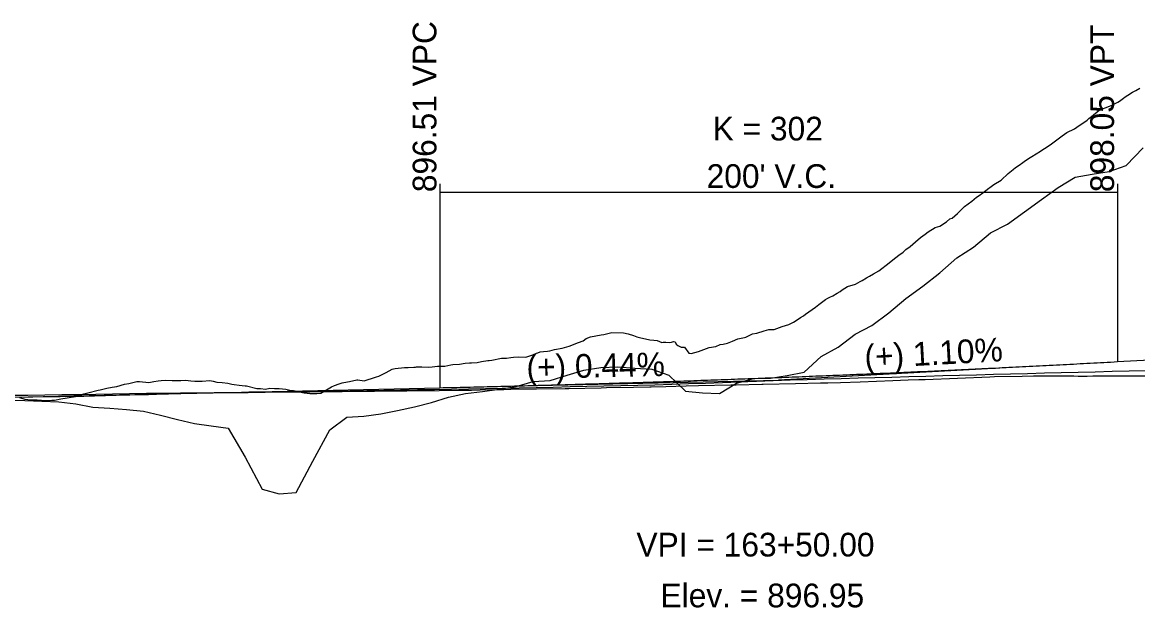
# Model space of a CAD drawing. Extents: x 1475774 to 1484571, y 1098511 to 1113011.
# Drawn here: x 1478897.8 to 1479227, y 1103928.9 to 1104101.6 of the extents above; entities that cross this region are included whole.
import ezdxf

# ---------------------------------------------------------------- set-up
doc = ezdxf.new("R2010")
doc.units = 0
for name, color, linetype in [('RD_DDB_GradeTX', 7, 'Continuous'), ('RD_DDB_PointTX', 7, 'Continuous'), ('RD_DDB_Profile_EX', 7, 'Continuous'), ('RD_DDB_Profile_Lbl', 7, 'Continuous'), ('RD_DDB_Profile_PR', 7, 'Continuous'), ('RD_DDB_StripGrade', 7, 'Continuous'), ('RD_DDB_VCLbl', 7, 'Continuous'), ('RD_Sketch2', 7, 'Continuous'), ('RD_Sketch3', 7, 'Continuous')]:
    doc.layers.add(name, color=color, linetype=linetype)

msp = doc.modelspace()

# ---------------------------------------------------------------- linework, layer by layer
at = {"layer": 'RD_DDB_GradeTX'}
for p in [(1479200.86, 1104000.39), (1479041, 1103994.24)]:
    msp.add_line(p, (1479120.98, 1103996), dxfattribs=at)
at = {"layer": 'RD_DDB_PointTX'}
for points in [[(1478894.42, 1103991.56), (1478899.42, 1103991.63), (1478904.42, 1103991.71), (1478909.42, 1103991.78), (1478914.42, 1103991.85), (1478919.42, 1103991.92), (1478924.42, 1103992), (1478929.42, 1103992.07), (1478934.42, 1103992.15), (1478939.42, 1103992.2), (1478944.42, 1103992.25), (1478949.42, 1103992.3), (1478954.42, 1103992.35), (1478959.42, 1103992.39), (1478964.42, 1103992.44), (1478969.42, 1103992.49), (1478974.42, 1103992.54), (1478979.42, 1103992.6), (1478984.42, 1103992.69), (1478989.42, 1103992.78), (1478994.42, 1103992.87), (1478999.42, 1103992.96), (1479004.42, 1103993.05), (1479009.42, 1103993.14), (1479014.42, 1103993.23), (1479019.42, 1103993.32), (1479024.42, 1103993.41), (1479029.42, 1103993.5), (1479034.42, 1103993.59), (1479039.42, 1103993.7), (1479044.42, 1103993.8), (1479049.42, 1103993.91), (1479054.42, 1103994.01), (1479059.42, 1103994.12), (1479064.42, 1103994.23), (1479069.42, 1103994.34), (1479074.42, 1103994.44), (1479079.42, 1103994.55), (1479084.42, 1103994.65), (1479089.42, 1103994.83), (1479094.42, 1103995.01), (1479099.42, 1103995.19), (1479104.42, 1103995.37), (1479109.42, 1103995.54), (1479114.42, 1103995.72), (1479119.42, 1103995.9), (1479124.42, 1103996.08), (1479129.42, 1103996.26), (1479134.42, 1103996.43), (1479139.42, 1103996.56), (1479144.42, 1103996.7), (1479149.42, 1103996.83), (1479154.42, 1103996.96), (1479159.42, 1103997.11), (1479164.42, 1103997.24)], [(1479164.42, 1103997.24), (1479169.42, 1103997.38), (1479174.42, 1103997.51), (1479179.42, 1103997.65), (1479184.42, 1103997.79), (1479189.42, 1103997.92), (1479194.42, 1103998.04), (1479199.42, 1103998.17), (1479204.42, 1103998.29), (1479209.42, 1103998.41), (1479214.42, 1103998.53), (1479219.42, 1103998.66), (1479224.42, 1103998.78), (1479229.42, 1103998.91)]]:
    msp.add_lwpolyline(points, dxfattribs=at)
at = {"layer": 'RD_DDB_Profile_EX'}
for points in [[(1479163.54, 1104023.72), (1479168.54, 1104027.68), (1479173.54, 1104032.08), (1479178.54, 1104035.32), (1479183.54, 1104039.47), (1479188.54, 1104042.1), (1479193.54, 1104045.74), (1479198.54, 1104049.38), (1479203.54, 1104052.85), (1479208.54, 1104055.91), (1479213.54, 1104056.84), (1479218.54, 1104057.57), (1479223.54, 1104059.33), (1479228.54, 1104064.6)], [(1478893.54, 1103990.17), (1478898.54, 1103990.02), (1478903.54, 1103989.87), (1478908.54, 1103989.67), (1478913.54, 1103989.07), (1478918.54, 1103988.09), (1478923.54, 1103987.72), (1478928.54, 1103987.36), (1478933.54, 1103986.85), (1478938.54, 1103985.66), (1478943.54, 1103984.47), (1478948.54, 1103983.27), (1478953.54, 1103982.51), (1478958.54, 1103981.89), (1478963.54, 1103973.34), (1478968.54, 1103963.9), (1478973.54, 1103962.48), (1478978.54, 1103962.86), (1478983.54, 1103972.13), (1478988.54, 1103981.41), (1478993.54, 1103985.12), (1478998.54, 1103985.37), (1479003.54, 1103986.11), (1479008.54, 1103987.1), (1479013.54, 1103988.17), (1479018.54, 1103989.41), (1479023.54, 1103991), (1479028.54, 1103992.06), (1479033.54, 1103992.7), (1479038.54, 1103993.34), (1479043.54, 1103994.15), (1479048.54, 1103995.63), (1479053.54, 1103995.94), (1479058.54, 1103997.5), (1479063.54, 1103999.02), (1479068.54, 1103999.81), (1479073.54, 1103999.94), (1479078.54, 1103999.54), (1479083.54, 1103999.32), (1479088.54, 1103997.52), (1479093.54, 1103992.76), (1479098.54, 1103992.34), (1479103.54, 1103992.13), (1479108.54, 1103995.11), (1479113.54, 1103996.49), (1479118.54, 1103996.66), (1479123.54, 1103997.43), (1479128.54, 1103998.35), (1479133.54, 1104002.98), (1479138.54, 1104005.74), (1479143.54, 1104009.61), (1479148.54, 1104012.14), (1479153.54, 1104015.92), (1479158.54, 1104020.12), (1479163.54, 1104023.72)]]:
    msp.add_lwpolyline(points, dxfattribs=at)
at = {"layer": 'RD_DDB_Profile_PR'}
for p, q in [((1479220.98, 1104001.5), (1479495.98, 1104016.62)), ((1479220.98, 1104001.5), (1479495.98, 1104016.62)), ((1478430.98, 1103980.88), (1479020.98, 1103993.81)), ((1478430.98, 1103980.88), (1479020.98, 1103993.81))]:
    msp.add_line(p, q, dxfattribs=at)
msp.add_spline([(1479020.98, 1103993.81), (1479024.98, 1103993.89), (1479028.98, 1103993.99), (1479032.98, 1103994.08), (1479036.98, 1103994.18), (1479040.98, 1103994.28), (1479044.98, 1103994.38), (1479048.98, 1103994.48), (1479052.98, 1103994.59), (1479056.98, 1103994.7), (1479060.98, 1103994.81), (1479064.98, 1103994.93), (1479068.98, 1103995.05), (1479072.98, 1103995.17), (1479076.98, 1103995.29), (1479080.98, 1103995.42), (1479084.98, 1103995.55), (1479088.98, 1103995.68), (1479092.98, 1103995.81), (1479096.98, 1103995.95), (1479100.98, 1103996.09), (1479104.98, 1103996.23), (1479108.98, 1103996.38), (1479112.98, 1103996.52), (1479116.98, 1103996.67), (1479120.98, 1103996.82), (1479124.98, 1103996.98), (1479128.98, 1103997.14), (1479132.98, 1103997.3), (1479136.98, 1103997.46), (1479140.98, 1103997.63), (1479144.98, 1103997.8), (1479148.98, 1103997.97), (1479152.98, 1103998.14), (1479156.98, 1103998.32), (1479160.98, 1103998.5), (1479164.98, 1103998.68), (1479168.98, 1103998.86), (1479172.98, 1103999.05), (1479176.98, 1103999.24), (1479180.98, 1103999.43), (1479184.98, 1103999.62), (1479188.98, 1103999.82), (1479192.98, 1104000.02), (1479196.98, 1104000.23), (1479200.98, 1104000.43), (1479204.98, 1104000.64), (1479208.98, 1104000.85), (1479212.98, 1104001.06), (1479216.98, 1104001.28), (1479220.98, 1104001.5)], degree=3, dxfattribs=at)
msp.add_spline([(1479020.98, 1103993.81), (1479024.98, 1103993.89), (1479028.98, 1103993.99), (1479032.98, 1103994.08), (1479036.98, 1103994.18), (1479040.98, 1103994.28), (1479044.98, 1103994.38), (1479048.98, 1103994.48), (1479052.98, 1103994.59), (1479056.98, 1103994.7), (1479060.98, 1103994.81), (1479064.98, 1103994.93), (1479068.98, 1103995.05), (1479072.98, 1103995.17), (1479076.98, 1103995.29), (1479080.98, 1103995.42), (1479084.98, 1103995.55), (1479088.98, 1103995.68), (1479092.98, 1103995.81), (1479096.98, 1103995.95), (1479100.98, 1103996.09), (1479104.98, 1103996.23), (1479108.98, 1103996.38), (1479112.98, 1103996.52), (1479116.98, 1103996.67), (1479120.98, 1103996.82), (1479124.98, 1103996.98), (1479128.98, 1103997.14), (1479132.98, 1103997.3), (1479136.98, 1103997.46), (1479140.98, 1103997.63), (1479144.98, 1103997.8), (1479148.98, 1103997.97), (1479152.98, 1103998.14), (1479156.98, 1103998.32), (1479160.98, 1103998.5), (1479164.98, 1103998.68), (1479168.98, 1103998.86), (1479172.98, 1103999.05), (1479176.98, 1103999.24), (1479180.98, 1103999.43), (1479184.98, 1103999.62), (1479188.98, 1103999.82), (1479192.98, 1104000.02), (1479196.98, 1104000.23), (1479200.98, 1104000.43), (1479204.98, 1104000.64), (1479208.98, 1104000.85), (1479212.98, 1104001.06), (1479216.98, 1104001.28), (1479220.98, 1104001.5)], degree=3, dxfattribs=at)
at = {"layer": 'RD_DDB_VCLbl'}
for p, q in [((1479020.98, 1104054), (1479020.98, 1103993.81)), ((1479220.98, 1104054), (1479220.98, 1104001.5)), ((1479020.98, 1104051.5), (1479220.98, 1104051.5))]:
    msp.add_line(p, q, dxfattribs=at)
at = {"layer": 'RD_Sketch2'}
msp.add_lwpolyline([(1478896.9, 1103990.98), (1478900.87, 1103991.08), (1478906.43, 1103991.17), (1478908.88, 1103991.21), (1478915.07, 1103991.31), (1478915.95, 1103991.33), (1478925.47, 1103991.59), (1478933.62, 1103991.8), (1478935, 1103991.83), (1478937.38, 1103991.87), (1478944.52, 1103992.05), (1478954.05, 1103992.28), (1478958.71, 1103992.4), (1478959.2, 1103992.41), (1478963.57, 1103992.52), (1478964.65, 1103992.55), (1478973.1, 1103992.55), (1478976.78, 1103992.56), (1478978.55, 1103992.58), (1478982.62, 1103992.62), (1478992.14, 1103992.71), (1479001.67, 1103992.79), (1479006.63, 1103992.87), (1479011.23, 1103992.91), (1479020.79, 1103993.01), (1479026.62, 1103993.07), (1479028.65, 1103993.1), (1479030.35, 1103993.12), (1479032.91, 1103993.14), (1479039.92, 1103993.29), (1479041.93, 1103993.33), (1479049.48, 1103993.44), (1479057.95, 1103993.57), (1479059.04, 1103993.59), (1479068.6, 1103993.8), (1479070.22, 1103993.84), (1479078.16, 1103993.96), (1479082.99, 1103994.04), (1479083.41, 1103994.04), (1479087.72, 1103994.18), (1479093.67, 1103994.36), (1479097.29, 1103994.43), (1479106.85, 1103994.62), (1479108.5, 1103994.66), (1479116, 1103994.88), (1479116.41, 1103994.89), (1479125.97, 1103995.07), (1479133.35, 1103995.22), (1479133.94, 1103995.23), (1479135.53, 1103995.26), (1479139.27, 1103995.33), (1479145.09, 1103995.56), (1479154.66, 1103995.93), (1479159.2, 1103996.11), (1479162.32, 1103996.18), (1479164.22, 1103996.26), (1479173.78, 1103996.65), (1479183.34, 1103997.04), (1479184.68, 1103997.09), (1479192.9, 1103997.21), (1479196.24, 1103997.27), (1479202.46, 1103997.3), (1479208.07, 1103997.34), (1479209.43, 1103997.22), (1479210.09, 1103997.23), (1479212.03, 1103997.17), (1479213.68, 1103997.31), (1479221.59, 1103997.34), (1479231.15, 1103997.35)], dxfattribs=at)
at = {"layer": 'RD_Sketch3'}
msp.add_lwpolyline([(1478896.9, 1103990.87), (1478898.5, 1103990.47), (1478899.34, 1103990.33), (1478899.91, 1103990.24), (1478902.1, 1103990.27), (1478904.77, 1103990.02), (1478906.43, 1103990.11), (1478907.27, 1103990.16), (1478909.08, 1103990.5), (1478913.5, 1103991.21), (1478913.99, 1103991.37), (1478914.74, 1103991.63), (1478915.95, 1103991.97), (1478917.11, 1103992.29), (1478920.18, 1103993.07), (1478920.71, 1103993.17), (1478922.67, 1103993.7), (1478924.31, 1103993.94), (1478925.63, 1103994.18), (1478927.91, 1103994.82), (1478929.17, 1103995.05), (1478931.52, 1103995.63), (1478932.35, 1103995.61), (1478935.12, 1103995.36), (1478936.54, 1103995.65), (1478937.85, 1103995.81), (1478938.72, 1103995.91), (1478940.02, 1103995.99), (1478942, 1103995.94), (1478942.31, 1103995.94), (1478942.92, 1103995.95), (1478944.52, 1103995.98), (1478945.91, 1103996.02), (1478947.47, 1103995.88), (1478948.7, 1103995.73), (1478949.51, 1103995.76), (1478950.87, 1103995.71), (1478953.11, 1103995.97), (1478954.05, 1103995.75), (1478955.21, 1103995.47), (1478956.7, 1103995.35), (1478958.41, 1103995.1), (1478959.55, 1103994.82), (1478960.3, 1103994.74), (1478961.72, 1103994.56), (1478963.57, 1103994.38), (1478963.9, 1103994.34), (1478967, 1103993.6), (1478968.05, 1103993.58), (1478969.49, 1103993.35), (1478970.84, 1103993.66), (1478972.23, 1103993.6), (1478973.1, 1103993.61), (1478973.52, 1103993.62), (1478975.53, 1103993.34), (1478976.76, 1103993.1), (1478977.77, 1103993), (1478980.9, 1103992.33), (1478981.86, 1103992.17), (1478982.62, 1103992.14), (1478984.72, 1103992.07), (1478985.83, 1103992.23), (1478989.04, 1103994.11), (1478989.94, 1103994.43), (1478991.32, 1103994.95), (1478992.14, 1103995.25), (1478992.62, 1103995.37), (1478994.28, 1103995.64), (1478996.45, 1103996.14), (1478996.83, 1103996.11), (1478998.63, 1103995.88), (1478999.8, 1103996.2), (1479000.8, 1103996.5), (1479001.67, 1103996.77), (1479002.33, 1103996.97), (1479002.97, 1103997.2), (1479003.38, 1103997.41), (1479005.13, 1103998.29), (1479006.96, 1103999.25), (1479007.29, 1103999.37), (1479007.81, 1103999.46), (1479010.53, 1103999.75), (1479011.23, 1103999.73), (1479011.62, 1103999.72), (1479013.29, 1103999.9), (1479013.79, 1103999.9), (1479014.11, 1103999.96), (1479015.65, 1103999.93), (1479017.69, 1103999.87), (1479018.77, 1104000.01), (1479020.28, 1104000.21), (1479020.79, 1104000.16), (1479021.26, 1104000.12), (1479022.44, 1104000.15), (1479024.24, 1104000.54), (1479024.84, 1104000.64), (1479026.77, 1104000.72), (1479028.42, 1104001.06), (1479029.71, 1104001.16), (1479030.35, 1104001.19), (1479032, 1104001.27), (1479033.26, 1104001.56), (1479035.17, 1104001.79), (1479035.58, 1104001.87), (1479036.36, 1104001.97), (1479039.16, 1104002.52), (1479039.92, 1104002.53), (1479040.63, 1104002.54), (1479041.91, 1104002.71), (1479042.74, 1104002.8), (1479044.07, 1104002.89), (1479046.33, 1104002.81), (1479048.4, 1104003.5), (1479049.48, 1104003.96), (1479049.91, 1104004.14), (1479050.56, 1104004.39), (1479051.54, 1104004.52), (1479052.72, 1104004.55), (1479053.5, 1104004.71), (1479054.88, 1104005.11), (1479057.08, 1104005.48), (1479059.21, 1104006.07), (1479061.9, 1104007.17), (1479063.29, 1104007.66), (1479064.21, 1104008.29), (1479065.49, 1104008.86), (1479068.6, 1104009.39), (1479069.4, 1104009.52), (1479071.76, 1104010.08), (1479075.19, 1104010.02), (1479076.61, 1104009.69), (1479078.16, 1104009.17), (1479079.14, 1104008.84), (1479079.91, 1104008.63), (1479082.98, 1104007.95), (1479084.18, 1104007.83), (1479085.15, 1104007.73), (1479086.48, 1104007.18), (1479086.93, 1104007.23), (1479087.72, 1104007.2), (1479088.92, 1104007.14), (1479089.32, 1104007.28), (1479090, 1104007.43), (1479090.44, 1104007.34), (1479090.77, 1104006.68), (1479091.28, 1104006.23), (1479092.21, 1104005.79), (1479093.21, 1104005.73), (1479094.45, 1104003.96), (1479095.21, 1104003.94), (1479097.29, 1104004.52), (1479098.11, 1104004.76), (1479100.44, 1104005.7), (1479102.43, 1104006), (1479103.75, 1104006.51), (1479104.59, 1104006.66), (1479105.86, 1104006.99), (1479106.85, 1104007.36), (1479107.35, 1104007.55), (1479108.91, 1104008.22), (1479110.94, 1104008.58), (1479111.26, 1104008.7), (1479113.23, 1104009.67), (1479114.54, 1104009.92), (1479116.67, 1104010.62), (1479118.14, 1104010.97), (1479119.71, 1104011.01), (1479122.07, 1104011.88), (1479124.03, 1104012.43), (1479125.34, 1104013.15), (1479126.19, 1104013.66), (1479127.47, 1104014.49), (1479128.35, 1104015.06), (1479128.94, 1104015.47), (1479131.88, 1104017.61), (1479132.87, 1104018.37), (1479134.83, 1104019.8), (1479135.53, 1104020.19), (1479136.14, 1104020.54), (1479136.99, 1104020.94), (1479138.26, 1104021.7), (1479139.15, 1104022.16), (1479139.74, 1104022.69), (1479141.31, 1104023.66), (1479143.65, 1104024.37), (1479145.09, 1104025.18), (1479145.62, 1104025.48), (1479146.95, 1104026.2), (1479147.78, 1104026.73), (1479149.03, 1104027.41), (1479150.55, 1104028.26), (1479153.64, 1104030.69), (1479154.66, 1104031.5), (1479156.42, 1104032.87), (1479157.76, 1104033.82), (1479158.57, 1104034.54), (1479159.78, 1104035.51), (1479161.37, 1104036.89), (1479162.89, 1104038.14), (1479164.22, 1104039.13), (1479165.16, 1104039.79), (1479167.21, 1104041.07), (1479168.59, 1104041.51), (1479170.52, 1104042.75), (1479171.52, 1104043.59), (1479172.19, 1104043.8), (1479173.78, 1104045.17), (1479175.89, 1104047.23), (1479178, 1104048.81), (1479179.41, 1104049.98), (1479180.15, 1104050.5), (1479181.25, 1104051.33), (1479183.03, 1104052.67), (1479183.34, 1104052.9), (1479184.47, 1104053.72), (1479186.64, 1104055.04), (1479188.78, 1104057.02), (1479190.25, 1104058.2), (1479190.94, 1104058.76), (1479191.96, 1104059.51), (1479193.1, 1104060.29), (1479193.86, 1104060.89), (1479195.25, 1104061.76), (1479197.48, 1104063.11), (1479197.83, 1104063.34), (1479201.09, 1104065.48), (1479202.66, 1104066.6), (1479203.88, 1104067.49), (1479204.71, 1104068.09), (1479206.04, 1104069.12), (1479208.33, 1104070.17), (1479209.01, 1104070.68), (1479212.03, 1104072.78), (1479212.51, 1104073.2), (1479213.34, 1104073.86), (1479215.56, 1104075.68), (1479218.67, 1104076.85), (1479219.18, 1104077.11), (1479221.13, 1104078.03), (1479221.59, 1104078.35), (1479222.8, 1104079.2), (1479223.29, 1104079.66), (1479224.01, 1104080.13), (1479225.44, 1104080.98), (1479226.42, 1104081.54), (1479227.6, 1104082.18)], dxfattribs=at)

# ---------------------------------------------------------------- texts
at = {"layer": 'RD_DDB_GradeTX'}
for s, rotation, p in [('(+) 1.10%', 3.1481, (1479146.51, 1103999.4)), ('(+) 0.44%', 1.2555, (1479046.63, 1103996.37))]:
    msp.add_text(s, height=7, rotation=rotation, dxfattribs=at).set_placement(p)
at = {"layer": 'RD_DDB_Profile_Lbl'}
for s, p in [('VPI = 163+50.00', (1479079.02, 1103944)), ('Elev. = 896.95', (1479086.13, 1103929))]:
    msp.add_text(s, height=7, dxfattribs=at).set_placement(p)
at = {"layer": 'RD_DDB_StripGrade'}
for s, p in [('896.51 VPC', (1479019.98, 1104051.5)), ('898.05 VPT', (1479219.98, 1104051.5))]:
    msp.add_text(s, height=7, rotation=90, dxfattribs=at).set_placement(p)
at = {"layer": 'RD_DDB_VCLbl'}
for s, p in [('K = 302', (1479101.51, 1104066.75)), ("200' V.C.", (1479099.73, 1104052.75))]:
    msp.add_text(s, height=7, dxfattribs=at).set_placement(p)

doc.saveas('drawing.dxf')
